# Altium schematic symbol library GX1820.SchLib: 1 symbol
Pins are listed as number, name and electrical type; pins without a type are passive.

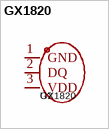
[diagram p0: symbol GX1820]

## GX1820
designator U?
footprint TO-92-3_L4.9-W3.7-P1.27-L
pins: 1 GND, 2 DQ, 3 VDD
